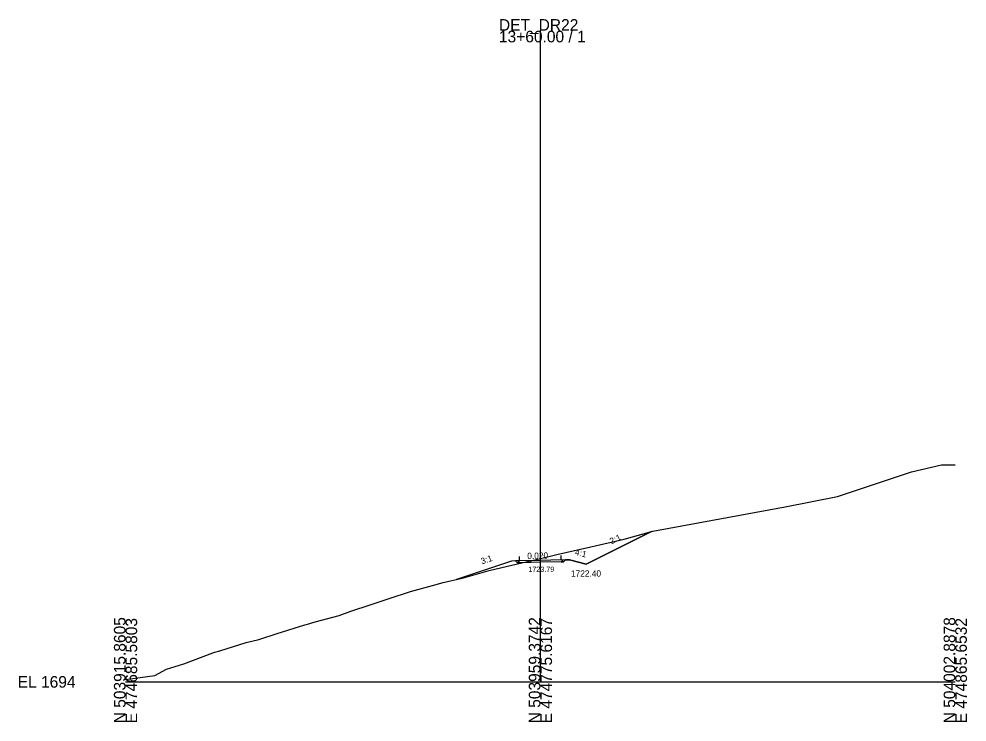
# Model space of a CAD drawing. Extents: x -26 to 1203, y -10 to 9633.
# Drawn here: x -25.7 to 202.8, y 8990.3 to 9159.9 of the extents above; entities that cross this region are included whole.
import ezdxf

# ---------------------------------------------------------------- set-up
doc = ezdxf.new("R2010")
doc.units = 0
for name, color, linetype in [('Exist Cross Section Cell', 7, 'Continuous'), ('Exist XS Center Line Elevation Label', 7, 'Continuous'), ('Exist XS Ground Line', 7, 'Continuous'), ('Prop XS Ditch Slope Text', 7, 'Continuous'), ('Prop XS Ditch Standard Text', 7, 'Continuous'), ('Prop XS Earthwork Shape', 7, 'Continuous'), ('Prop XS EOT Tick Mark', 7, 'Continuous'), ('Prop XS Finish Grade', 7, 'Continuous'), ('Prop XS Finish Grade Earthwork', 7, 'Continuous'), ('Prop XS Finish Grade Pavement', 7, 'Continuous'), ('Prop XS Pvmt Edge Slope', 7, 'Continuous'), ('Prop XS SE Text', 7, 'Continuous'), ('Prop XS Shoulder Borrow Shape', 7, 'Continuous'), ('Prop XS Side Slope Text', 7, 'Continuous'), ('Prop XS Subgrade Earthwork', 7, 'Continuous')]:
    doc.layers.add(name, color=color, linetype=linetype)

msp = doc.modelspace()

# ---------------------------------------------------------------- linework, layer by layer
at = {"layer": 'Exist Cross Section Cell'}
for p, q in [((100, 9000), (100, 9157.07)), ((0, 9000), (100, 9000)), ((100, 9000), (200, 9000))]:
    msp.add_line(p, q, dxfattribs=at)
at = {"layer": 'Exist XS Ground Line'}
msp.add_lwpolyline([(0, 9000.56), (7.07, 9001.52), (9.9, 9003.09), (14.07, 9004.36), (21.01, 9006.98), (21.56, 9007.2), (22.69, 9007.52), (29.05, 9009.5), (32.12, 9010.24), (36.54, 9011.64), (43.23, 9013.78), (43.88, 9013.89), (45.68, 9014.47), (51.51, 9016.05), (54.33, 9017.03), (59, 9018.62), (65.44, 9020.77), (66.49, 9021.09), (68.67, 9021.76), (73.98, 9023.28), (76.55, 9023.97), (81.47, 9025.11), (87.66, 9026.83), (92.04, 9027.95), (100, 9029.79), (104, 9030.72), (112.15, 9032.55), (120.21, 9034.46), (127.1, 9036.37), (158.97, 9042.26), (171.58, 9044.72), (189.42, 9050.68), (196.67, 9052.34), (200, 9052.36)], dxfattribs=at)
at = {"layer": 'Prop XS Earthwork Shape'}
for points in [[(100, 9028.84), (95.51, 9028.75), (100, 9029.79), (104, 9030.72), (112.15, 9032.55), (120.21, 9034.46), (126.74, 9036.27), (111, 9028.4), (107, 9029.4), (106.02, 9029.44), (105.53, 9028.95), (105, 9028.94)], [(93, 9029.12), (79.79, 9024.72), (81.47, 9025.11), (87.66, 9026.83), (92.04, 9027.95), (95.51, 9028.75), (95, 9028.74), (94.45, 9028.73), (93.98, 9029.2)]]:
    msp.add_lwpolyline(points, close=True, dxfattribs=at)
at = {"layer": 'Prop XS EOT Tick Mark'}
for p, q in [((95, 9029.28), (95, 9030.28)), ((105, 9029.48), (105, 9030.48))]:
    msp.add_line(p, q, dxfattribs=at)
at = {"layer": 'Prop XS Finish Grade'}
for p, q in [((105, 9029.48), (106.02, 9029.44)), ((95, 9029.28), (93.98, 9029.2))]:
    msp.add_line(p, q, dxfattribs=at)
at = {"layer": 'Prop XS Finish Grade Earthwork'}
for p, q in [((111, 9028.4), (126.74, 9036.27)), ((106.02, 9029.44), (107, 9029.4)), ((107, 9029.4), (111, 9028.4)), ((93, 9029.12), (79.79, 9024.72)), ((93.98, 9029.2), (93, 9029.12))]:
    msp.add_line(p, q, dxfattribs=at)
at = {"layer": 'Prop XS Finish Grade Pavement'}
for p, q in [((95, 9029.28), (100, 9029.38)), ((100, 9029.38), (105, 9029.48))]:
    msp.add_line(p, q, dxfattribs=at)
at = {"layer": 'Prop XS Pvmt Edge Slope'}
for p, q in [((105, 9029.48), (105.53, 9028.95)), ((95, 9029.28), (94.45, 9028.73))]:
    msp.add_line(p, q, dxfattribs=at)
at = {"layer": 'Prop XS Shoulder Borrow Shape'}
for points in [[(105, 9029.48), (106.02, 9029.44), (105.53, 9028.95)], [(95, 9029.28), (93.98, 9029.2), (94.45, 9028.73)]]:
    msp.add_lwpolyline(points, close=True, dxfattribs=at)
at = {"layer": 'Prop XS Subgrade Earthwork'}
for p, q in [((105.53, 9028.95), (106.02, 9029.44)), ((94.45, 9028.73), (93.98, 9029.2)), ((95, 9028.74), (94.45, 9028.73)), ((100, 9028.84), (95, 9028.74)), ((105, 9028.94), (100, 9028.84)), ((105, 9028.94), (105.53, 9028.95))]:
    msp.add_line(p, q, dxfattribs=at)

# ---------------------------------------------------------------- texts
at = {"layer": 'Exist Cross Section Cell'}
for s, p in [('DET_DR22', (90, 9157.07)), ('13+60.00 / 1', (90, 9154.27)), ('EL 1694', (-26, 8998.6))]:
    msp.add_text(s, height=2.8, dxfattribs=at).set_placement(p)
for s, p in [('N 503915.8605', (0, 8990)), ('E 474685.5803', (2.8, 8990)), ('N 503959.3742', (100, 8990)), ('E 474775.6167', (102.8, 8990)), ('N 504002.8878', (200, 8990)), ('E 474865.6532', (202.8, 8990))]:
    msp.add_text(s, height=2.8, rotation=90, dxfattribs=at).set_placement(p)
at = {"layer": 'Exist XS Center Line Elevation Label'}
msp.add_text('1723.79', height=1.25, dxfattribs=at).set_placement((97.09, 9026.54))
at = {"layer": 'Prop XS Ditch Slope Text'}
msp.add_text('4:1', height=1.5, rotation=345.9638, dxfattribs=at).set_placement((108.21, 9030.65))
at = {"layer": 'Prop XS Ditch Standard Text'}
msp.add_text('1722.40', height=1.5, dxfattribs=at).set_placement((107.37, 9025.4))
at = {"layer": 'Prop XS SE Text'}
msp.add_text('0.020', height=1.5, rotation=1.1458, dxfattribs=at).set_placement((96.85, 9029.64))
at = {"layer": 'Prop XS Side Slope Text'}
for s, rotation, p in [('2:1', 26.5651, (117.14, 9033.15)), ('3:1', 18.4349, (85.92, 9028.34))]:
    msp.add_text(s, height=1.5, rotation=rotation, dxfattribs=at).set_placement(p)

doc.saveas('drawing.dxf')
